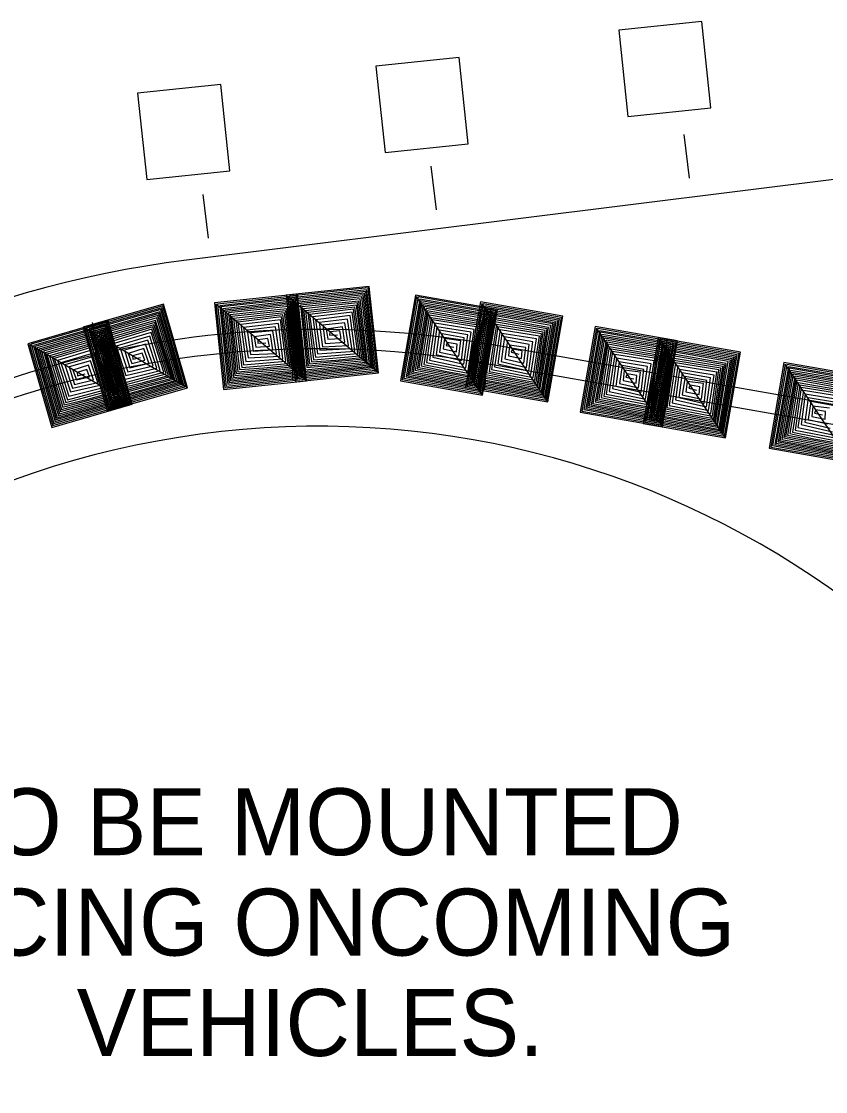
# Model space of a CAD drawing. Extents: x 640253 to 641999, y 298458 to 299646.
# Drawn here: x 641527.81 to 641563.88, y 299475.25 to 299523.22 of the extents above; entities that cross this region are included whole.
import ezdxf

# ---------------------------------------------------------------- set-up
doc = ezdxf.new("R2010")
doc.units = 0
doc.layers.add('2', color=7, linetype='Continuous')

msp = doc.modelspace()

# ---------------------------------------------------------------- linework, layer by layer
at = {"layer": '2'}
for p, q in [((641581.99, 299518.351), (641535.213, 299512.52)), ((641557.777, 299516.199), (641557.534, 299518.16)), ((641546.425, 299514.776), (641546.181, 299516.737)), ((641536.202, 299513.51), (641535.959, 299515.47)), ((641539.986, 299507.156), (641539.95, 299510.785)), ((641548.596, 299506.739), (641548.873, 299510.368)), ((641531.654, 299506.149), (641530.994, 299509.724)), ((641590.633, 299501.412), (641548.769, 299508.754)), ((641556.179, 299505.351), (641556.771, 299508.943)), ((641540.211, 299508.545), (641540.211, 299508.545)), ((641548.613, 299507.904), (641548.613, 299507.904)), ((641590.477, 299500.543), (641548.613, 299507.885)), ((641531.863, 299507.556), (641531.863, 299507.556))]:
    msp.add_line(p, q, dxfattribs=at)
for points in [[(641558.736, 299519.349), (641558.325, 299523.224), (641554.598, 299522.833), (641555.008, 299518.956)], [(641547.846, 299517.735), (641547.436, 299521.61), (641543.709, 299521.218), (641544.119, 299517.341)], [(641537.159, 299516.524), (641536.748, 299520.399), (641533.021, 299520.008), (641533.431, 299516.131)]]:
    msp.add_lwpolyline(points, close=True, dxfattribs=at)
for points in [[(641543.819, 299507.468), (641543.41, 299511.347), (641539.686, 299510.951), (641540.096, 299507.074), (641543.819, 299507.468), (641539.758, 299510.897), (641540.156, 299507.147), (641543.765, 299507.528), (641543.367, 299511.278), (641539.827, 299510.903), (641540.213, 299507.228), (641543.686, 299507.595), (641543.306, 299511.191), (641539.925, 299510.828), (641540.296, 299507.305), (641543.621, 299507.658), (641543.256, 299511.12), (641539.99, 299510.774), (641540.348, 299507.383), (641543.554, 299507.72), (641543.198, 299511.037), (641540.067, 299510.695), (641540.409, 299507.458), (641543.492, 299507.772), (641543.135, 299510.962), (641540.15, 299510.624), (641540.475, 299507.533), (641543.419, 299507.833), (641543.075, 299510.884), (641540.225, 299510.564), (641540.538, 299507.607), (641543.334, 299507.884), (641543.006, 299510.789), (641540.321, 299510.505), (641540.606, 299507.705), (641543.277, 299507.947), (641542.94, 299510.685), (641540.39, 299510.422), (641540.667, 299507.787), (641543.202, 299508.016), (641542.89, 299510.601), (641540.454, 299510.345), (641540.733, 299507.872), (641543.154, 299508.091), (641542.831, 299510.505), (641540.544, 299510.255), (641540.815, 299507.97), (641541.913, 299508.037), (641543.079, 299508.16), (641542.763, 299510.42), (641540.65, 299510.168), (641540.913, 299508.06), (641542.994, 299508.239), (641542.702, 299510.326), (641540.736, 299510.089), (641540.998, 299508.174), (641542.894, 299508.337), (641542.65, 299510.193), (641540.875, 299509.985), (641541.092, 299508.322), (641542.756, 299508.441), (641542.559, 299510.037), (641540.996, 299509.851), (641541.198, 299508.489), (641542.625, 299508.566), (641542.625, 299508.572), (641542.436, 299509.876), (641541.156, 299509.732), (641541.313, 299508.639), (641542.481, 299508.693), (641542.315, 299509.708), (641541.327, 299509.612), (641541.431, 299508.791), (641542.311, 299508.845), (641542.209, 299509.539), (641541.473, 299509.432), (641541.55, 299508.972), (641542.154, 299509.014), (641542.088, 299509.351), (641541.644, 299509.303), (641541.631, 299509.155), (641541.99, 299509.172)], [(641535.251, 299506.805), (641534.174, 299510.553), (641530.576, 299509.517), (641531.653, 299505.769), (641535.251, 299506.805), (641530.655, 299509.476), (641531.699, 299505.853), (641535.187, 299506.855), (641534.143, 299510.478), (641530.722, 299509.494), (641531.741, 299505.942), (641535.097, 299506.907), (641534.099, 299510.382), (641530.832, 299509.438), (641531.809, 299506.032), (641535.022, 299506.957), (641534.062, 299510.303), (641530.905, 299509.394), (641531.847, 299506.117), (641534.947, 299507.007), (641534.02, 299510.211), (641530.995, 299509.33), (641531.893, 299506.203), (641534.876, 299507.046), (641533.97, 299510.126), (641531.089, 299509.275), (641531.947, 299506.288), (641534.793, 299507.094), (641533.924, 299510.04), (641531.174, 299509.23), (641531.995, 299506.371), (641534.701, 299507.13), (641533.874, 299509.934), (641531.278, 299509.188), (641532.045, 299506.48), (641534.635, 299507.182), (641533.826, 299509.819), (641531.36, 299509.117), (641532.091, 299506.571), (641534.549, 299507.236), (641533.791, 299509.728), (641531.437, 299509.053), (641532.143, 299506.667), (641534.489, 299507.303), (641533.751, 299509.623), (641531.541, 299508.98), (641532.205, 299506.778), (641533.274, 299507.034), (641534.401, 299507.357), (641533.697, 299509.528), (641531.662, 299508.913), (641532.287, 299506.882), (641534.303, 299507.419), (641533.655, 299509.426), (641531.76, 299508.851), (641532.349, 299507.009), (641534.189, 299507.498), (641533.626, 299509.284), (641531.914, 299508.771), (641532.416, 299507.171), (641534.035, 299507.578), (641533.564, 299509.115), (641532.057, 299508.661), (641532.493, 299507.355), (641533.885, 299507.678), (641533.882, 299507.684), (641533.47, 299508.936), (641532.235, 299508.571), (641532.578, 299507.521), (641533.72, 299507.778), (641533.38, 299508.748), (641532.424, 299508.482), (641532.67, 299507.692), (641533.526, 299507.898), (641533.305, 299508.563), (641532.599, 299508.332), (641532.755, 299507.892), (641533.343, 299508.038), (641533.218, 299508.359), (641532.791, 299508.234), (641532.803, 299508.086), (641533.153, 299508.165)], [(641540.594, 299507.118), (641540.186, 299510.997), (641536.461, 299510.601), (641536.871, 299506.724), (641540.594, 299507.118), (641536.534, 299510.547), (641536.931, 299506.797), (641540.54, 299507.179), (641540.142, 299510.929), (641536.602, 299510.554), (641536.988, 299506.879), (641540.461, 299507.245), (641540.081, 299510.841), (641536.7, 299510.479), (641537.071, 299506.956), (641540.396, 299507.308), (641540.031, 299510.77), (641536.765, 299510.424), (641537.123, 299507.033), (641540.329, 299507.37), (641539.973, 299510.687), (641536.842, 299510.345), (641537.184, 299507.108), (641540.267, 299507.422), (641539.91, 299510.612), (641536.925, 299510.274), (641537.25, 299507.183), (641540.194, 299507.483), (641539.85, 299510.535), (641537, 299510.214), (641537.313, 299507.258), (641540.108, 299507.535), (641539.781, 299510.439), (641537.096, 299510.156), (641537.381, 299507.356), (641540.052, 299507.597), (641539.715, 299510.335), (641537.165, 299510.072), (641537.442, 299507.437), (641539.977, 299507.666), (641539.665, 299510.252), (641537.229, 299509.995), (641537.508, 299507.522), (641539.929, 299507.741), (641539.606, 299510.156), (641537.319, 299509.906), (641537.59, 299507.62), (641538.688, 299507.687), (641539.854, 299507.81), (641539.538, 299510.07), (641537.425, 299509.818), (641537.688, 299507.71), (641539.769, 299507.889), (641539.477, 299509.976), (641537.51, 299509.739), (641537.773, 299507.824), (641539.669, 299507.987), (641539.425, 299509.843), (641537.65, 299509.635), (641537.867, 299507.972), (641539.531, 299508.091), (641539.334, 299509.687), (641537.771, 299509.502), (641537.973, 299508.139), (641539.4, 299508.216), (641539.4, 299508.222), (641539.211, 299509.526), (641537.931, 299509.383), (641538.088, 299508.289), (641539.256, 299508.343), (641539.09, 299509.358), (641538.102, 299509.262), (641538.206, 299508.441), (641539.086, 299508.495), (641538.983, 299509.189), (641538.248, 299509.083), (641538.325, 299508.622), (641538.929, 299508.664), (641538.863, 299509.002), (641538.419, 299508.954), (641538.406, 299508.806), (641538.765, 299508.822)], [(641548.496, 299506.472), (641549.167, 299510.314), (641545.477, 299510.958), (641544.806, 299507.116), (641548.496, 299506.472), (641545.534, 299510.885), (641544.885, 299507.17), (641548.459, 299506.545), (641549.106, 299510.26), (641545.6, 299510.872), (641544.963, 299507.233), (641548.402, 299506.631), (641549.025, 299510.193), (641545.673, 299510.772), (641545.063, 299507.285), (641548.356, 299506.71), (641548.956, 299510.139), (641545.721, 299510.704), (641545.133, 299507.343), (641548.311, 299506.787), (641548.877, 299510.074), (641545.773, 299510.606), (641545.213, 299507.399), (641548.265, 299506.854), (641548.798, 299510.018), (641545.834, 299510.516), (641545.298, 299507.454), (641548.211, 299506.933), (641548.719, 299509.962), (641545.89, 299510.437), (641545.377, 299507.508), (641548.142, 299507.006), (641548.625, 299509.889), (641545.967, 299510.354), (641545.471, 299507.583), (641548.106, 299507.081), (641548.534, 299509.806), (641546.008, 299510.256), (641545.552, 299507.645), (641548.052, 299507.168), (641548.463, 299509.741), (641546.05, 299510.162), (641545.64, 299507.708), (641548.027, 299507.254), (641548.379, 299509.664), (641546.111, 299510.052), (641545.744, 299507.781), (641546.819, 299507.543), (641547.973, 299507.341), (641548.29, 299509.601), (641546.19, 299509.939), (641545.863, 299507.839), (641547.913, 299507.441), (641548.206, 299509.526), (641546.25, 299509.839), (641545.977, 299507.927), (641547.844, 299507.562), (641548.119, 299509.414), (641546.356, 299509.702), (641546.106, 299508.043), (641547.74, 299507.699), (641547.988, 299509.289), (641546.436, 299509.539), (641546.256, 299508.174), (641547.648, 299507.856), (641547.65, 299507.862), (641547.827, 299509.168), (641546.556, 299509.381), (641546.406, 299508.287), (641547.546, 299508.018), (641547.665, 299509.039), (641546.688, 299509.218), (641546.563, 299508.399), (641547.423, 299508.21), (641547.515, 299508.906), (641546.779, 299509.006), (641546.727, 299508.541), (641547.319, 299508.416), (641547.348, 299508.758), (641546.909, 299508.835), (641546.854, 299508.695), (641547.204, 299508.614)], [(641551.419, 299506.17), (641552.09, 299510.012), (641548.4, 299510.656), (641547.729, 299506.814), (641551.419, 299506.17), (641548.456, 299510.583), (641547.809, 299506.868), (641551.381, 299506.243), (641552.029, 299509.958), (641548.523, 299510.57), (641547.885, 299506.931), (641551.325, 299506.329), (641551.948, 299509.891), (641548.596, 299510.47), (641547.986, 299506.983), (641551.279, 299506.408), (641551.879, 299509.837), (641548.644, 299510.401), (641548.056, 299507.041), (641551.233, 299506.485), (641551.8, 299509.772), (641548.696, 299510.304), (641548.135, 299507.097), (641551.188, 299506.552), (641551.721, 299509.716), (641548.756, 299510.214), (641548.221, 299507.151), (641551.133, 299506.631), (641551.642, 299509.66), (641548.813, 299510.135), (641548.3, 299507.206), (641551.065, 299506.704), (641551.548, 299509.587), (641548.89, 299510.052), (641548.394, 299507.281), (641551.029, 299506.779), (641551.456, 299509.504), (641548.931, 299509.954), (641548.475, 299507.343), (641550.975, 299506.866), (641551.385, 299509.439), (641548.973, 299509.86), (641548.563, 299507.406), (641550.95, 299506.952), (641551.302, 299509.362), (641549.034, 299509.749), (641548.667, 299507.479), (641549.742, 299507.241), (641550.896, 299507.039), (641551.213, 299509.299), (641549.113, 299509.637), (641548.785, 299507.537), (641550.836, 299507.139), (641551.129, 299509.224), (641549.173, 299509.537), (641548.9, 299507.624), (641550.767, 299507.26), (641551.042, 299509.112), (641549.279, 299509.399), (641549.029, 299507.741), (641550.663, 299507.397), (641550.91, 299508.987), (641549.358, 299509.237), (641549.179, 299507.872), (641550.571, 299507.554), (641550.573, 299507.56), (641550.75, 299508.866), (641549.479, 299509.079), (641549.329, 299507.985), (641550.469, 299507.716), (641550.588, 299508.737), (641549.611, 299508.916), (641549.486, 299508.097), (641550.346, 299507.908), (641550.438, 299508.604), (641549.702, 299508.704), (641549.65, 299508.239), (641550.242, 299508.114), (641550.271, 299508.456), (641549.831, 299508.533), (641549.777, 299508.393), (641550.127, 299508.312)], [(641532.769, 299506.062), (641531.692, 299509.81), (641528.094, 299508.774), (641529.171, 299505.026), (641532.769, 299506.062), (641528.173, 299508.733), (641529.217, 299505.11), (641532.704, 299506.112), (641531.66, 299509.735), (641528.24, 299508.752), (641529.258, 299505.199), (641532.615, 299506.164), (641531.617, 299509.639), (641528.35, 299508.695), (641529.327, 299505.289), (641532.54, 299506.214), (641531.579, 299509.56), (641528.423, 299508.651), (641529.365, 299505.374), (641532.465, 299506.264), (641531.538, 299509.468), (641528.513, 299508.587), (641529.41, 299505.46), (641532.394, 299506.304), (641531.488, 299509.383), (641528.606, 299508.533), (641529.465, 299505.545), (641532.311, 299506.351), (641531.442, 299509.297), (641528.692, 299508.487), (641529.513, 299505.629), (641532.219, 299506.387), (641531.392, 299509.191), (641528.796, 299508.445), (641529.563, 299505.737), (641532.152, 299506.439), (641531.344, 299509.077), (641528.877, 299508.374), (641529.608, 299505.829), (641532.067, 299506.493), (641531.309, 299508.985), (641528.954, 299508.31), (641529.66, 299505.924), (641532.006, 299506.56), (641531.269, 299508.881), (641529.059, 299508.237), (641529.723, 299506.035), (641530.792, 299506.291), (641531.919, 299506.614), (641531.215, 299508.785), (641529.179, 299508.17), (641529.804, 299506.139), (641531.821, 299506.677), (641531.173, 299508.683), (641529.277, 299508.108), (641529.867, 299506.266), (641531.706, 299506.756), (641531.144, 299508.541), (641529.431, 299508.029), (641529.934, 299506.429), (641531.552, 299506.835), (641531.081, 299508.372), (641529.575, 299507.918), (641530.01, 299506.612), (641531.402, 299506.935), (641531.4, 299506.941), (641530.988, 299508.193), (641529.752, 299507.829), (641530.096, 299506.779), (641531.238, 299507.035), (641530.898, 299508.006), (641529.942, 299507.739), (641530.188, 299506.949), (641531.044, 299507.156), (641530.823, 299507.82), (641530.117, 299507.589), (641530.273, 299507.149), (641530.861, 299507.295), (641530.736, 299507.616), (641530.309, 299507.491), (641530.321, 299507.343), (641530.671, 299507.422)], [(641556.563, 299505.06), (641557.233, 299508.901), (641553.544, 299509.545), (641552.873, 299505.704), (641556.563, 299505.06), (641553.6, 299509.472), (641552.952, 299505.758), (641556.525, 299505.133), (641557.173, 299508.847), (641553.667, 299509.46), (641553.029, 299505.82), (641556.469, 299505.218), (641557.092, 299508.781), (641553.74, 299509.36), (641553.129, 299505.872), (641556.423, 299505.297), (641557.023, 299508.726), (641553.788, 299509.291), (641553.2, 299505.931), (641556.377, 299505.374), (641556.944, 299508.662), (641553.84, 299509.193), (641553.279, 299505.987), (641556.331, 299505.441), (641556.865, 299508.606), (641553.9, 299509.104), (641553.365, 299506.041), (641556.277, 299505.52), (641556.785, 299508.549), (641553.956, 299509.024), (641553.444, 299506.095), (641556.209, 299505.593), (641556.692, 299508.476), (641554.034, 299508.941), (641553.538, 299506.17), (641556.173, 299505.668), (641556.6, 299508.393), (641554.075, 299508.843), (641553.619, 299506.233), (641556.119, 299505.756), (641556.529, 299508.329), (641554.117, 299508.749), (641553.706, 299506.295), (641556.094, 299505.841), (641556.446, 299508.252), (641554.177, 299508.639), (641553.811, 299506.368), (641554.885, 299506.131), (641556.04, 299505.929), (641556.356, 299508.189), (641554.256, 299508.526), (641553.929, 299506.427), (641555.979, 299506.029), (641556.273, 299508.114), (641554.317, 299508.427), (641554.044, 299506.514), (641555.91, 299506.149), (641556.186, 299508.002), (641554.423, 299508.289), (641554.173, 299506.631), (641555.806, 299506.287), (641556.054, 299507.877), (641554.502, 299508.127), (641554.323, 299506.762), (641555.715, 299506.443), (641555.717, 299506.449), (641555.894, 299507.756), (641554.623, 299507.968), (641554.473, 299506.874), (641555.613, 299506.606), (641555.731, 299507.627), (641554.754, 299507.806), (641554.629, 299506.987), (641555.49, 299506.797), (641555.581, 299507.493), (641554.846, 299507.593), (641554.794, 299507.129), (641555.385, 299507.004), (641555.415, 299507.345), (641554.975, 299507.422), (641554.921, 299507.283), (641555.271, 299507.202)], [(641559.385, 299504.556), (641560.056, 299508.397), (641556.367, 299509.041), (641555.696, 299505.199), (641559.385, 299504.556), (641556.423, 299508.968), (641555.775, 299505.254), (641559.348, 299504.629), (641559.996, 299508.343), (641556.49, 299508.956), (641555.852, 299505.316), (641559.292, 299504.714), (641559.915, 299508.276), (641556.563, 299508.856), (641555.952, 299505.368), (641559.246, 299504.793), (641559.846, 299508.222), (641556.611, 299508.787), (641556.023, 299505.427), (641559.2, 299504.87), (641559.767, 299508.158), (641556.663, 299508.689), (641556.102, 299505.483), (641559.154, 299504.937), (641559.688, 299508.101), (641556.723, 299508.599), (641556.188, 299505.537), (641559.1, 299505.016), (641559.608, 299508.045), (641556.779, 299508.52), (641556.267, 299505.591), (641559.031, 299505.089), (641559.515, 299507.972), (641556.856, 299508.437), (641556.361, 299505.666), (641558.996, 299505.164), (641559.423, 299507.889), (641556.898, 299508.339), (641556.442, 299505.729), (641558.942, 299505.252), (641559.352, 299507.824), (641556.94, 299508.245), (641556.529, 299505.791), (641558.917, 299505.337), (641559.269, 299507.747), (641557, 299508.135), (641556.633, 299505.864), (641557.709, 299505.627), (641558.863, 299505.424), (641559.179, 299507.685), (641557.079, 299508.022), (641556.752, 299505.922), (641558.802, 299505.524), (641559.096, 299507.61), (641557.14, 299507.922), (641556.867, 299506.01), (641558.733, 299505.645), (641559.008, 299507.497), (641557.246, 299507.785), (641556.996, 299506.127), (641558.629, 299505.783), (641558.877, 299507.372), (641557.325, 299507.622), (641557.146, 299506.258), (641558.538, 299505.939), (641558.54, 299505.945), (641558.717, 299507.252), (641557.446, 299507.464), (641557.296, 299506.37), (641558.436, 299506.101), (641558.554, 299507.122), (641557.577, 299507.302), (641557.452, 299506.483), (641558.313, 299506.293), (641558.404, 299506.989), (641557.669, 299507.089), (641557.617, 299506.624), (641558.209, 299506.499), (641558.238, 299506.841), (641557.798, 299506.918), (641557.744, 299506.779), (641558.094, 299506.697)], [(641565.702, 299507.287), (641562.013, 299507.931), (641561.342, 299504.089), (641565.031, 299503.445), (641562.069, 299507.858), (641561.421, 299504.143), (641564.994, 299503.518)], [(641565.642, 299507.233), (641562.135, 299507.845), (641561.498, 299504.206), (641564.938, 299503.604)], [(641565.561, 299507.166), (641562.209, 299507.745), (641561.598, 299504.258), (641564.892, 299503.683)], [(641565.492, 299507.112), (641562.256, 299507.677), (641561.669, 299504.316), (641564.846, 299503.76)], [(641565.413, 299507.047), (641562.309, 299507.579), (641561.748, 299504.372), (641564.8, 299503.827)], [(641565.334, 299506.991), (641562.369, 299507.489), (641561.834, 299504.427), (641564.746, 299503.906)], [(641565.254, 299506.935), (641562.425, 299507.41), (641561.913, 299504.481), (641564.677, 299503.979)], [(641565.16, 299506.862), (641562.502, 299507.327), (641562.006, 299504.556), (641564.642, 299504.054)], [(641565.069, 299506.779), (641562.544, 299507.229), (641562.088, 299504.618), (641564.588, 299504.141)], [(641564.998, 299506.714), (641562.586, 299507.135), (641562.175, 299504.681), (641564.563, 299504.226)], [(641564.915, 299506.637), (641562.646, 299507.024), (641562.279, 299504.754), (641563.354, 299504.516), (641564.508, 299504.314)], [(641564.825, 299506.574), (641562.725, 299506.912), (641562.398, 299504.812), (641564.448, 299504.414)], [(641564.742, 299506.499), (641562.785, 299506.812), (641562.513, 299504.899), (641564.379, 299504.535)], [(641564.654, 299506.387), (641562.892, 299506.674), (641562.642, 299505.016), (641564.275, 299504.672)], [(641564.523, 299506.262), (641562.971, 299506.512), (641562.792, 299505.147), (641564.184, 299504.829)], [(641564.363, 299506.141), (641563.092, 299506.354), (641562.942, 299505.26), (641564.081, 299504.991)], [(641564.2, 299506.012), (641563.223, 299506.191), (641563.098, 299505.372), (641563.959, 299505.183)], [(641564.05, 299505.879), (641563.315, 299505.979), (641563.263, 299505.514), (641563.854, 299505.389), (641563.883, 299505.731), (641563.444, 299505.808), (641563.39, 299505.668), (641563.74, 299505.587)]]:
    msp.add_lwpolyline(points, dxfattribs=at)
for radius, start, end in [(47.733, 97.1018, 132.2976), (44.262, 80.0428, 132.2178), (43.393, 80.0478, 246.9218), (39.921, 13.5395, 270)]:
    msp.add_arc((641541.114, 299465.152), radius, start, end, dxfattribs=at)

# ---------------------------------------------------------------- texts
for s, p in [('TO BE MOUNTED', (641524.046, 299485.846)), ('FACING ONCOMING', (641521.046, 299481.346)), (' VEHICLES.', (641529.172, 299476.846))]:
    msp.add_text(s, height=3, dxfattribs=at).set_placement(p)

doc.saveas('drawing.dxf')
